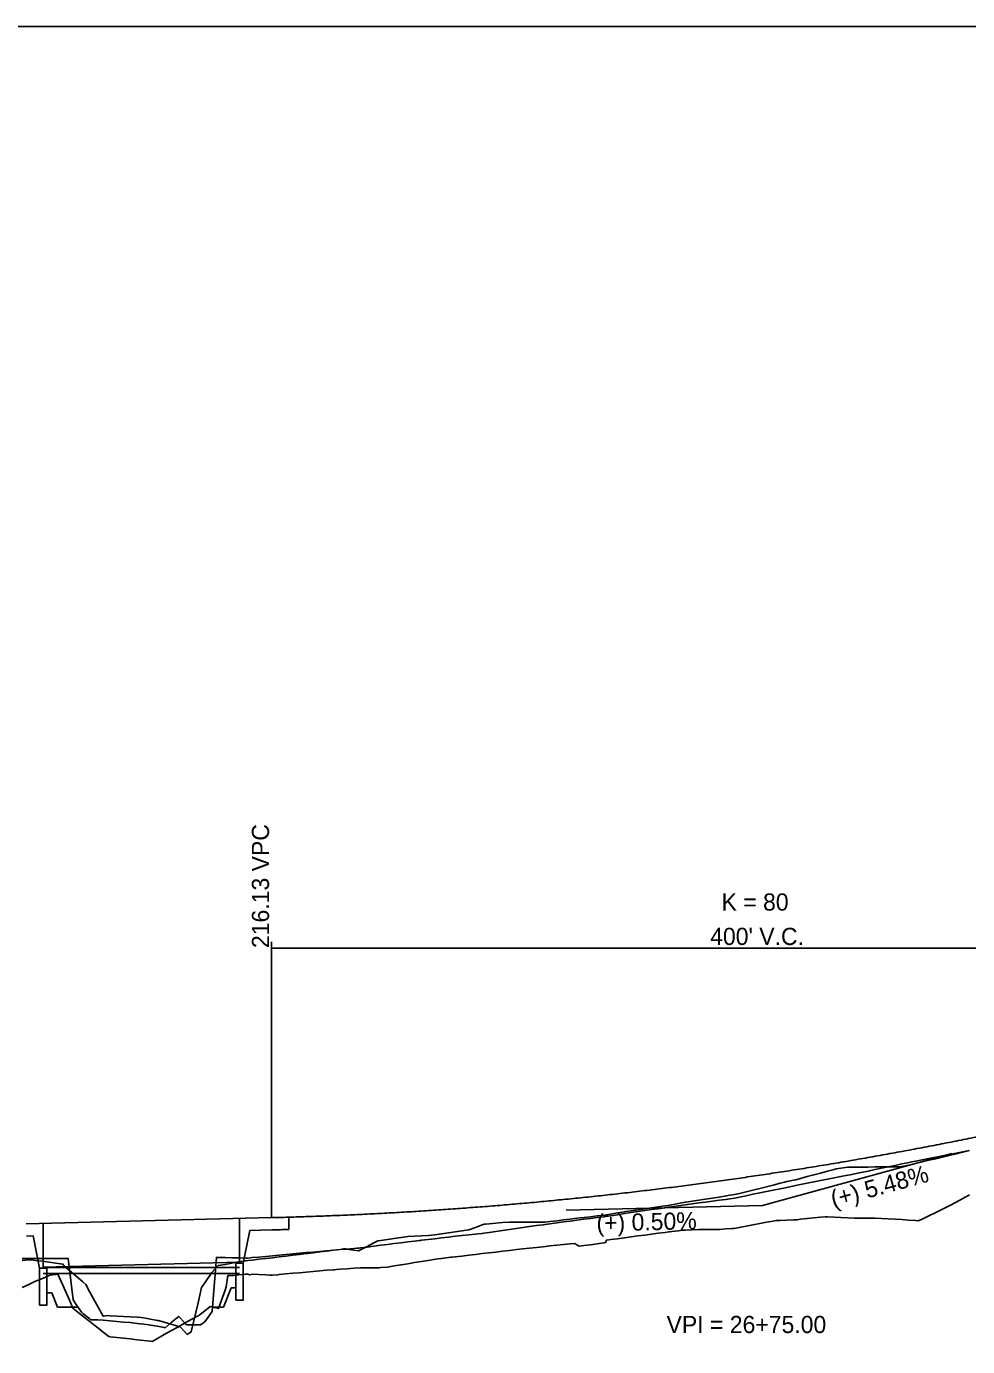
# Model space of a CAD drawing. Extents: x 2224795 to 2228395, y 930927 to 933127.
# Drawn here: x 2226430 to 2226814, y 932017 to 932554 of the extents above; entities that cross this region are included whole.
import ezdxf

# ---------------------------------------------------------------- set-up
doc = ezdxf.new("R2010")
doc.units = 0
for name, color, linetype in [('BR_CONCRETE', 7, 'Continuous'), ('BR_EXIST_GROUND_LT', 7, 'Continuous'), ('BR_EXIST_GROUND_RT', 7, 'Continuous'), ('BR_USER NOTES', 7, 'Continuous'), ('RD_DDB_GradeTX', 7, 'Continuous'), ('RD_DDB_Profile_EX', 7, 'Continuous'), ('RD_DDB_Profile_Lbl', 7, 'Continuous'), ('RD_DDB_Profile_PR', 7, 'Continuous'), ('RD_DDB_StripGrade', 7, 'Continuous'), ('RD_DDB_VCLbl', 7, 'Continuous'), ('RD_SHT_ShtClip', 7, 'Continuous')]:
    doc.layers.add(name, color=color, linetype=linetype)

msp = doc.modelspace()

# ---------------------------------------------------------------- linework, layer by layer
at = {"layer": 'BR_CONCRETE'}
for p, q in [((2226437.06, 932066.83), (2226437.06, 932048.97)), ((2226517.06, 932068.83), (2226517.06, 932050.97)), ((2226537.06, 932064.34), (2226537.06, 932069.35)), ((2226430.19, 932061.66), (2226432.93, 932061.72)), ((2226435.56, 932048.56), (2226432.93, 932061.72)), ((2226518.56, 932050.56), (2226521.24, 932063.93)), ((2226521.24, 932063.93), (2226530.19, 932064.16)), ((2226437.06, 932048.97), (2226517.06, 932050.97)), ((2226437.06, 932048.56), (2226437.06, 932048.97)), ((2226517.06, 932050.56), (2226517.06, 932050.97)), ((2226438.56, 932038.56), (2226440.56, 932038.56)), ((2226440.56, 932038.56), (2226442.89, 932032.74)), ((2226513.56, 932040.56), (2226510.44, 932032.74)), ((2226515.56, 932040.56), (2226513.56, 932040.56)), ((2226442.89, 932032.74), (2226451.2, 932032.74)), ((2226506.03, 932032.74), (2226510.44, 932032.74))]:
    msp.add_line(p, q, dxfattribs=at)
for points in [[(2226435.56, 932048.56), (2226438.56, 932048.56), (2226438.56, 932033.56), (2226435.56, 932033.56)], [(2226518.56, 932050.56), (2226515.56, 932050.56), (2226515.56, 932035.56), (2226518.56, 932035.56)]]:
    msp.add_lwpolyline(points, close=True, dxfattribs=at)
msp.add_open_spline([(2226530.2, 932064.16), (2226532.31, 932064.21), (2226534.6, 932064.28), (2226536.89, 932064.34), (2226537.06, 932064.34)], degree=3, dxfattribs=at)
at = {"layer": 'BR_EXIST_GROUND_LT'}
msp.add_lwpolyline([(2226428.41, 932040.71), (2226431.17, 932041.97), (2226433.93, 932043.22), (2226436.68, 932044.44), (2226439.73, 932045.78), (2226442.2, 932046.07), (2226442.93, 932046.16), (2226445.02, 932041.7), (2226447.71, 932035.58), (2226449.14, 932032.33), (2226450.47, 932031.27), (2226453.23, 932029.08), (2226455.99, 932026.88), (2226458.74, 932024.68), (2226459.78, 932023.85), (2226461.5, 932022.5), (2226463.74, 932020.74), (2226464.26, 932020.68), (2226467.02, 932020.38), (2226469.78, 932020.08), (2226472.53, 932019.77), (2226475.29, 932019.46), (2226478.05, 932019.14), (2226480.81, 932018.82), (2226481.39, 932018.76), (2226483.56, 932019.97), (2226486.32, 932021.52), (2226489.08, 932023.06), (2226491.84, 932024.6), (2226494.6, 932026.14), (2226497.35, 932027.69), (2226500.11, 932029.22), (2226500.99, 932029.71), (2226502.87, 932031.24), (2226505, 932032.96), (2226505.63, 932032.81), (2226508.46, 932032.13), (2226511.14, 932039.6), (2226511.65, 932041.01), (2226512.33, 932045.65), (2226513.9, 932045.62), (2226514.57, 932045.61), (2226516.66, 932045.82), (2226519.42, 932046.08), (2226520.42, 932046.18), (2226521.14, 932045.89), (2226522.19, 932046.18), (2226524.93, 932046), (2226527.69, 932045.81), (2226529.35, 932045.69), (2226530.45, 932045.77), (2226532.65, 932045.92), (2226533.2, 932045.98), (2226535.96, 932046.23), (2226538.72, 932046.49), (2226541.48, 932046.74), (2226544.24, 932046.99), (2226546.99, 932047.23), (2226549.75, 932047.47), (2226552.51, 932047.7), (2226555.27, 932047.93), (2226555.71, 932047.97), (2226556.59, 932048.02), (2226558.02, 932048.14), (2226560.78, 932048.37), (2226563.8, 932048.62), (2226566.3, 932048.67), (2226569.05, 932048.71), (2226571.81, 932048.74), (2226573.97, 932048.75), (2226574.57, 932048.81), (2226577.33, 932049.05), (2226577.97, 932049.11), (2226580.09, 932049.48), (2226582.84, 932049.95), (2226585.6, 932050.41), (2226588.36, 932050.87), (2226591.12, 932051.31), (2226593.87, 932051.75), (2226596.85, 932052.21), (2226599.39, 932052.53), (2226602.15, 932052.87), (2226603.13, 932053), (2226603.63, 932053.04), (2226604.91, 932053.2), (2226607.66, 932053.53), (2226610.42, 932053.86), (2226613.18, 932054.18), (2226615.94, 932054.51), (2226618.69, 932054.82), (2226621.45, 932055.14), (2226624.21, 932055.45), (2226626.97, 932055.76), (2226628.16, 932055.9), (2226629.86, 932056.14), (2226632.48, 932056.43), (2226635.24, 932056.73), (2226638, 932057.03), (2226640.76, 932057.32), (2226643.51, 932057.61), (2226646.27, 932057.9), (2226649.03, 932058.18), (2226651.79, 932058.46), (2226653.66, 932058.65), (2226654.54, 932058.08), (2226655.44, 932057.51), (2226657.3, 932057.76), (2226660.06, 932058.14), (2226662.82, 932058.53), (2226665.58, 932058.93), (2226666.3, 932059.04), (2226666.39, 932059.92), (2226667.54, 932060.09), (2226668.33, 932060.2), (2226671.09, 932060.58), (2226673.85, 932060.96), (2226676.61, 932061.34), (2226679.36, 932061.71), (2226682.12, 932062.08), (2226684.88, 932062.44), (2226687.64, 932062.8), (2226690.4, 932063.15), (2226691.93, 932063.34), (2226692.3, 932063.39), (2226693.15, 932063.5), (2226695.91, 932063.84), (2226697.4, 932064.03), (2226698.67, 932064.09), (2226701.43, 932064.2), (2226704.18, 932064.28), (2226706.94, 932064.34), (2226709.7, 932064.38), (2226712.76, 932064.39), (2226715.22, 932064.58), (2226717.57, 932064.75), (2226717.97, 932064.75), (2226718.32, 932064.75), (2226718.64, 932064.77), (2226720.73, 932065.2), (2226723.49, 932065.75), (2226726.25, 932066.28), (2226729, 932066.79), (2226731.76, 932067.27), (2226734.52, 932067.74), (2226735.72, 932067.93), (2226737.28, 932068.03), (2226740.04, 932068.17), (2226742.79, 932068.28), (2226744.26, 932068.33), (2226745.55, 932068.48), (2226748.31, 932068.78), (2226751.07, 932069.06), (2226753.82, 932069.3), (2226755.64, 932069.45), (2226756.58, 932069.43), (2226759.34, 932069.33), (2226762.1, 932069.2), (2226764.85, 932069.05), (2226767.61, 932068.88), (2226770.37, 932068.93), (2226773.13, 932068.96), (2226773.79, 932068.96), (2226775.89, 932068.91), (2226778.64, 932068.83), (2226781.4, 932068.71), (2226784.16, 932068.57), (2226786.92, 932068.39), (2226789.67, 932068.18), (2226792.43, 932067.95), (2226793.55, 932067.84), (2226795.19, 932068.58), (2226797.95, 932069.87), (2226800.71, 932071.2), (2226803.46, 932072.57), (2226806.22, 932073.97), (2226808.98, 932075.42), (2226811.74, 932076.9), (2226814.49, 932078.43)], dxfattribs=at)
at = {"layer": 'BR_EXIST_GROUND_RT'}
msp.add_lwpolyline([(2226428.41, 932051.69), (2226431.17, 932051.95), (2226432.04, 932052.04), (2226433.93, 932051.77), (2226436.68, 932051.39), (2226439.44, 932051.01), (2226442.2, 932050.63), (2226445.05, 932050.25), (2226445.89, 932049.14), (2226447.71, 932047.62), (2226450.47, 932045.32), (2226453.23, 932043.02), (2226454.38, 932041.94), (2226455.99, 932038.79), (2226458.74, 932033.87), (2226461.46, 932029.02), (2226463.31, 932029.24), (2226464.26, 932029.19), (2226467.02, 932029.05), (2226469.78, 932028.91), (2226472.53, 932028.77), (2226475.29, 932028.63), (2226476.89, 932028.55), (2226478.05, 932028.34), (2226480.81, 932027.82), (2226483.56, 932027.31), (2226484.06, 932027.21), (2226486.32, 932026.55), (2226489.08, 932025.75), (2226491.84, 932024.94), (2226492.89, 932024.63), (2226494.6, 932022.81), (2226495.7, 932021.61), (2226497.35, 932022.62), (2226500.11, 932034.43), (2226501.57, 932040.66), (2226502.87, 932042.56), (2226505.8, 932046.84), (2226508.38, 932049.63), (2226511.14, 932050.12), (2226513.9, 932050.62), (2226516.66, 932051.13), (2226519.42, 932051.63), (2226520.4, 932051.7), (2226522.17, 932051.9), (2226524.93, 932052.21), (2226527.69, 932052.53), (2226530.45, 932052.85), (2226533.2, 932053.18), (2226535.96, 932053.51), (2226538.72, 932053.84), (2226541.48, 932054.18), (2226544.24, 932054.51), (2226544.86, 932054.55), (2226546.99, 932054.82), (2226549.75, 932055.17), (2226552.51, 932055.52), (2226555.27, 932055.87), (2226558.02, 932056.23), (2226559.38, 932056.41), (2226560.18, 932056.47), (2226560.78, 932056.38), (2226563.54, 932055.97), (2226565.67, 932055.66), (2226566.3, 932055.99), (2226569.05, 932057.44), (2226571.81, 932058.89), (2226573.45, 932059.75), (2226574.57, 932059.91), (2226577.33, 932060.31), (2226580.09, 932060.7), (2226582.84, 932061.1), (2226584.84, 932061.38), (2226585.6, 932061.43), (2226588.36, 932061.6), (2226591.12, 932061.77), (2226593.87, 932061.94), (2226596.63, 932062.12), (2226599.39, 932062.52), (2226602.15, 932062.92), (2226604.91, 932063.33), (2226607.66, 932063.74), (2226610.42, 932064.21), (2226613.18, 932065.19), (2226615.94, 932066.17), (2226616.77, 932066.47), (2226617.22, 932066.53), (2226618.69, 932066.68), (2226621.45, 932066.97), (2226624.21, 932067.24), (2226626.97, 932067.26), (2226629.73, 932067.27), (2226632.48, 932067.29), (2226635.24, 932067.31), (2226638, 932067.33), (2226640.76, 932067.35), (2226641.42, 932067.36), (2226643.51, 932067.6), (2226646.27, 932067.92), (2226649.03, 932068.24), (2226651.79, 932068.56), (2226654.54, 932068.88), (2226657.47, 932069.23), (2226660.06, 932069.52), (2226662.82, 932069.83), (2226665.8, 932070.17), (2226666.4, 932070.24), (2226668.33, 932070.57), (2226671.09, 932071.05), (2226673.85, 932071.54), (2226674.39, 932071.63), (2226676.61, 932071.95), (2226679.36, 932072.35), (2226682.12, 932072.74), (2226684.88, 932073.14), (2226687.64, 932073.55), (2226690.4, 932073.95), (2226690.87, 932074.02), (2226693.15, 932074.43), (2226695.91, 932074.92), (2226698.67, 932075.41), (2226699.01, 932075.47), (2226701.43, 932075.84), (2226704.18, 932076.26), (2226706.94, 932076.68), (2226709.7, 932077.11), (2226712.46, 932077.53), (2226715.33, 932077.98), (2226716.79, 932078.25), (2226717.97, 932078.44), (2226719.46, 932078.67), (2226720.73, 932078.99), (2226723.49, 932079.67), (2226726.25, 932080.36), (2226729, 932081.05), (2226731.76, 932081.75), (2226734.52, 932082.45), (2226737.28, 932083.14), (2226739.08, 932083.6), (2226740.04, 932083.81), (2226742.79, 932084.42), (2226743.67, 932084.61), (2226745.55, 932085.11), (2226748.31, 932085.85), (2226751.07, 932086.59), (2226753.82, 932087.33), (2226756.58, 932088.07), (2226759.34, 932088.82), (2226760.1, 932089.02), (2226762.1, 932089.3), (2226764.85, 932089.69), (2226765.44, 932089.78), (2226767.61, 932089.77), (2226770.37, 932089.76), (2226773.13, 932089.77), (2226775.89, 932089.79), (2226778.64, 932089.81), (2226781.4, 932089.85), (2226784.16, 932089.84), (2226785.9, 932089.83), (2226786.92, 932090.03), (2226789.67, 932090.57), (2226790.97, 932090.82), (2226792.43, 932091.18), (2226795.19, 932091.84), (2226797.95, 932092.51), (2226800.71, 932093.17), (2226803.46, 932093.84), (2226806.22, 932094.5), (2226808.98, 932095.16), (2226810.56, 932095.54), (2226811.74, 932095.82), (2226814.49, 932096.48)], dxfattribs=at)
at = {"layer": 'BR_USER NOTES'}
for p, q in [((2226437.06, 932048.91), (2226437.06, 932066.76)), ((2226437.06, 932048.91), (2226517.06, 932048.91)), ((2226437.06, 932046.41), (2226517.06, 932046.41))]:
    msp.add_line(p, q, dxfattribs=at)
at = {"layer": 'RD_DDB_GradeTX'}
for p in [(2226807.22, 932095.29), (2226650.09, 932072.15)]:
    msp.add_line(p, (2226730.06, 932074.15), dxfattribs=at)
at = {"layer": 'RD_DDB_Profile_EX'}
msp.add_lwpolyline([(2226428.41, 932052.53), (2226431.17, 932052.54), (2226433.93, 932052.55), (2226436.68, 932052.56), (2226439.44, 932052.56), (2226442.2, 932052.56), (2226444.96, 932052.56), (2226447.15, 932052.55), (2226447.71, 932048.06), (2226449.22, 932035.68), (2226450.47, 932033.81), (2226452.61, 932030.64), (2226452.91, 932030.37), (2226453.23, 932030.11), (2226455.99, 932027.88), (2226456.45, 932027.51), (2226458.74, 932027.57), (2226459.26, 932027.59), (2226461.5, 932027.39), (2226464.26, 932027.14), (2226467.02, 932026.9), (2226469.78, 932026.65), (2226472.53, 932026.4), (2226475.29, 932026.09), (2226478.05, 932025.78), (2226480.06, 932025.55), (2226480.81, 932025.42), (2226483.56, 932024.91), (2226486.32, 932024.4), (2226486.74, 932024.33), (2226489.08, 932026.28), (2226491.84, 932028.57), (2226492.24, 932028.9), (2226494.6, 932026.43), (2226495.44, 932025.55), (2226497.35, 932025.53), (2226500.11, 932025.51), (2226501.14, 932025.5), (2226502.87, 932026.7), (2226505.88, 932030.87), (2226507.62, 932052.94), (2226508.38, 932052.93), (2226511.14, 932052.86), (2226513.9, 932052.8), (2226516.66, 932052.73), (2226519.67, 932052.66), (2226520.48, 932052.69), (2226522.17, 932052.86), (2226524.93, 932053.12), (2226527.69, 932053.38), (2226530.45, 932053.65), (2226533.2, 932053.91), (2226535.96, 932054.16), (2226538.72, 932054.42), (2226541.48, 932054.67), (2226544.24, 932054.93), (2226544.71, 932054.97), (2226545.45, 932055.02), (2226546.99, 932055.16), (2226549.75, 932055.41), (2226552.51, 932055.65), (2226555.27, 932055.9), (2226558.02, 932056.14), (2226560.78, 932056.38), (2226563.54, 932056.62), (2226564.81, 932056.73), (2226565.82, 932056.78), (2226566.3, 932056.85), (2226569.05, 932057.2), (2226571.81, 932057.55), (2226574.57, 932057.9), (2226577.33, 932058.25), (2226580.09, 932058.59), (2226582.84, 932058.94), (2226585.6, 932059.27), (2226588.36, 932059.61), (2226590.2, 932059.83), (2226590.76, 932059.89), (2226591.12, 932059.93), (2226593.87, 932060.26), (2226596.63, 932060.59), (2226599.39, 932060.91), (2226602.15, 932061.23), (2226604.91, 932061.55), (2226607.66, 932061.87), (2226610.42, 932062.18), (2226613.18, 932062.48), (2226614.26, 932062.6), (2226615.94, 932062.76), (2226616.59, 932062.83), (2226618.69, 932063.14), (2226621.45, 932063.55), (2226624.21, 932063.95), (2226626.97, 932064.35), (2226629.73, 932064.74), (2226632.48, 932065.13), (2226635.24, 932065.52), (2226638, 932065.91), (2226640.76, 932066.29), (2226641.55, 932066.4), (2226643.51, 932066.66), (2226646.27, 932067.04), (2226649.03, 932067.41), (2226651.79, 932067.77), (2226654.54, 932068.14), (2226657.3, 932068.5), (2226660.06, 932068.85), (2226662.82, 932069.2), (2226665.58, 932069.55), (2226665.98, 932069.6), (2226666.72, 932069.7), (2226667.24, 932069.77), (2226668.33, 932069.94), (2226671.09, 932070.36), (2226673.85, 932070.78), (2226676.61, 932071.19), (2226679.36, 932071.6), (2226682.12, 932072.01), (2226684.88, 932072.41), (2226687.64, 932072.81), (2226690.4, 932073.21), (2226691.8, 932073.41), (2226693.15, 932073.6), (2226695.91, 932073.99), (2226698.67, 932074.37), (2226701.43, 932074.75), (2226704.18, 932075.13), (2226706.94, 932075.51), (2226709.7, 932075.88), (2226712.46, 932076.24), (2226715.22, 932076.6), (2226716.79, 932076.81), (2226717.97, 932076.96), (2226718.7, 932077.06), (2226720.73, 932077.49), (2226723.49, 932078.07), (2226726.25, 932078.66), (2226729, 932079.23), (2226731.76, 932079.81), (2226734.52, 932080.38), (2226737.28, 932080.94), (2226740.04, 932081.5), (2226743.06, 932082.12), (2226743.69, 932082.25), (2226745.55, 932082.62), (2226748.31, 932083.17), (2226751.07, 932083.72), (2226753.82, 932084.27), (2226756.58, 932084.81), (2226759.34, 932085.34), (2226762.1, 932085.88), (2226764.88, 932086.41), (2226765.98, 932086.63), (2226767.61, 932086.98), (2226770.37, 932087.57), (2226773.13, 932088.15), (2226775.89, 932088.74), (2226778.64, 932089.32), (2226781.4, 932089.89), (2226784.16, 932090.46), (2226786.92, 932091.03), (2226789.94, 932091.65), (2226790.95, 932091.85), (2226792.43, 932092.15), (2226795.19, 932092.71), (2226797.95, 932093.26), (2226800.71, 932093.81), (2226803.46, 932094.36), (2226806.22, 932094.9), (2226808.98, 932095.44), (2226811.74, 932095.98), (2226813.08, 932096.24), (2226814.49, 932096.51)], dxfattribs=at)
at = {"layer": 'RD_DDB_Profile_PR'}
msp.add_line((2226430.06, 932066.65), (2226530.06, 932069.15), dxfattribs=at)
msp.add_spline([(2226530.06, 932069.15), (2226538.06, 932069.37), (2226546.06, 932069.63), (2226554.06, 932069.93), (2226562.06, 932070.27), (2226570.06, 932070.65), (2226578.06, 932071.07), (2226586.06, 932071.53), (2226594.06, 932072.03), (2226602.06, 932072.57), (2226610.06, 932073.15), (2226618.06, 932073.76), (2226626.06, 932074.42), (2226634.06, 932075.12), (2226642.06, 932075.86), (2226650.06, 932076.64), (2226658.06, 932077.45), (2226666.06, 932078.31), (2226674.06, 932079.21), (2226682.06, 932080.15), (2226690.06, 932081.12), (2226698.06, 932082.14), (2226706.06, 932083.2), (2226714.06, 932084.29), (2226722.06, 932085.43), (2226730.06, 932086.6), (2226738.06, 932087.82), (2226746.06, 932089.08), (2226754.06, 932090.37), (2226762.06, 932091.71), (2226770.06, 932093.08), (2226778.06, 932094.5), (2226786.06, 932095.95), (2226794.06, 932097.45), (2226802.06, 932098.98), (2226810.06, 932100.56), (2226818.06, 932102.17), (2226826.06, 932103.82), (2226834.06, 932105.52), (2226842.06, 932107.25), (2226850.06, 932109.03), (2226858.06, 932110.84), (2226866.06, 932112.69), (2226874.06, 932114.59), (2226882.06, 932116.52), (2226890.06, 932118.49), (2226898.06, 932120.5), (2226906.06, 932122.56), (2226914.06, 932124.65), (2226922.06, 932126.78), (2226930.06, 932128.95)], degree=3, dxfattribs=at)
at = {"layer": 'RD_DDB_VCLbl'}
for p, q in [((2226530.06, 932181.45), (2226530.06, 932069.15)), ((2226530.06, 932178.95), (2226930.06, 932178.95))]:
    msp.add_line(p, q, dxfattribs=at)
at = {"layer": 'RD_SHT_ShtClip'}
msp.add_lwpolyline([(2225474.62, 932554.3), (2227274.62, 932554.3), (2227274.62, 931454.3), (2225474.62, 931454.3)], close=True, dxfattribs=at)

# ---------------------------------------------------------------- texts
at = {"layer": 'RD_DDB_GradeTX'}
for s, rotation, p in [('(+) 5.48%', 15.323, (2226759.03, 932073.15)), ('(+) 0.50%', 1.4321, (2226662.56, 932063.46))]:
    msp.add_text(s, height=7, rotation=rotation, dxfattribs=at).set_placement(p)
at = {"layer": 'RD_DDB_Profile_Lbl'}
msp.add_text('VPI = 26+75.00', height=7, dxfattribs=at).set_placement((2226691.04, 932022.15))
at = {"layer": 'RD_DDB_StripGrade'}
msp.add_text('216.13 VPC', height=7, rotation=90, dxfattribs=at).set_placement((2226529.06, 932178.95))
at = {"layer": 'RD_DDB_VCLbl'}
for s, p in [('K = 80', (2226713.44, 932194.2)), ("400' V.C.", (2226708.81, 932180.2))]:
    msp.add_text(s, height=7, dxfattribs=at).set_placement(p)

doc.saveas('drawing.dxf')
